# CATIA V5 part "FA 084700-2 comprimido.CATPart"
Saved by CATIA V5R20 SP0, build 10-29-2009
Part number: FA 084700-2 comprimido
Revision: ANY
Definition: UNKNOWN
Nomenclature: FA 084700-2 comprimido
Source: Unknown
Bounding box of the stored display mesh (mm): x -2.45 to 2.45, y 0 to 4.72, z -2.45 to 2.45
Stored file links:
  C:\Users\Utente\Desktop\IO LAVORO\3D X SITO CF\CUMSA\3D files FA\FA 0847SF\FA 084700-2 comprimido.CATPart

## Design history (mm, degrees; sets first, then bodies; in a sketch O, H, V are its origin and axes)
Body1 "Cortar-Extruir1" (main body)
  Solid1: solid without history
